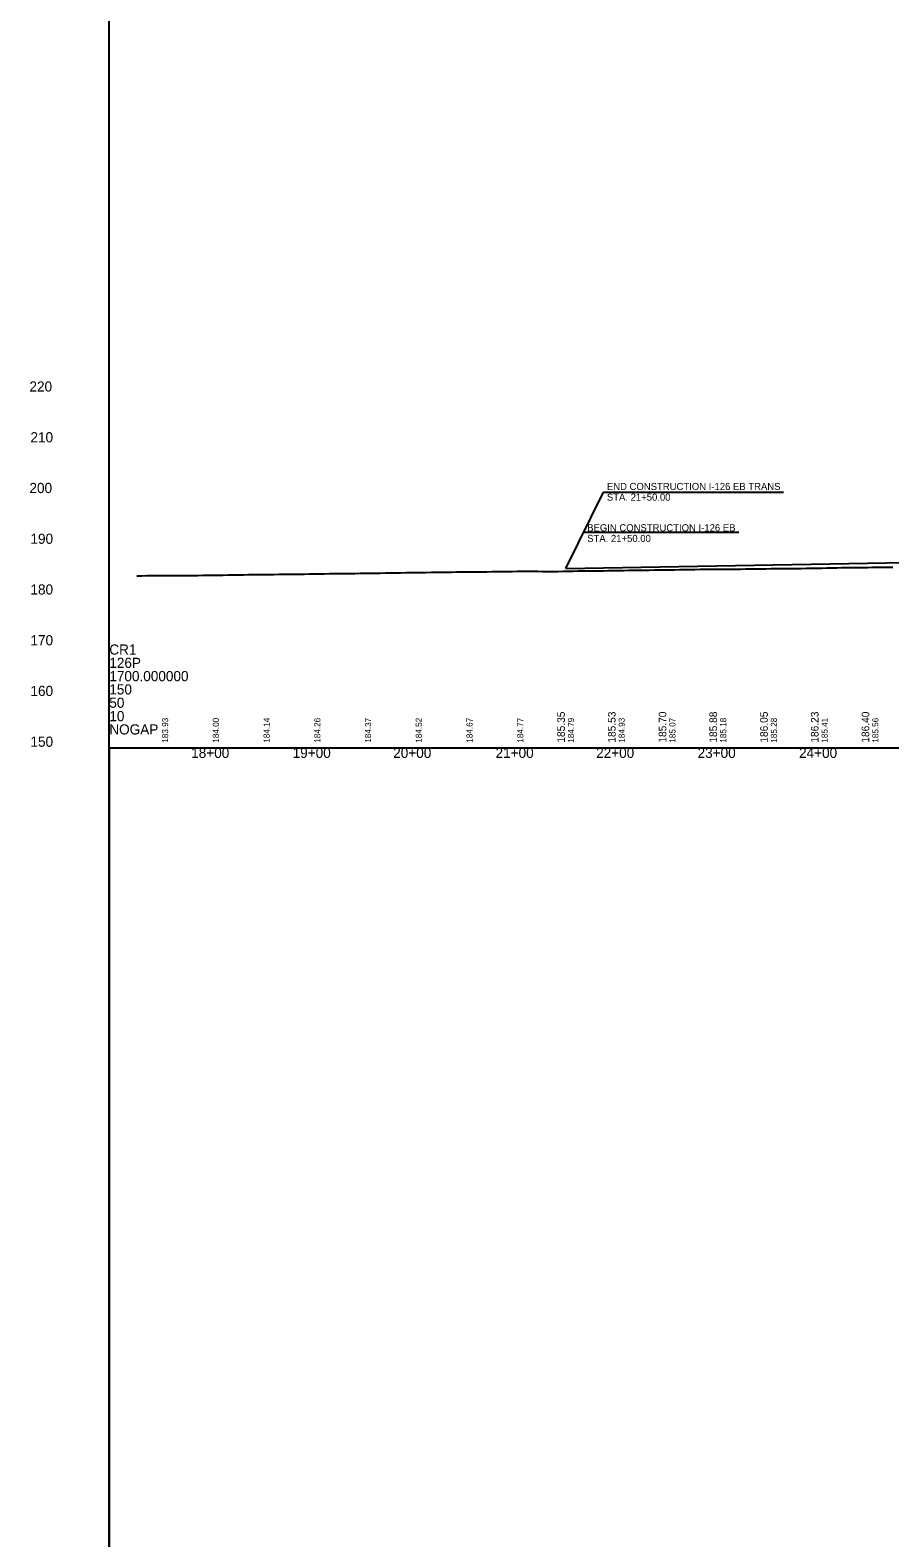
# Model space of a CAD drawing. Extents: x 69 to 2003113, y 512 to 837401.
# Drawn here: x 1888999 to 1889847, y 817230 to 818716 of the extents above; entities that cross this region are included whole.
import ezdxf

# ---------------------------------------------------------------- set-up
doc = ezdxf.new("R2010")
doc.units = 0
for name, color, linetype in [('BR_AUTO DIMENSION', 7, 'Continuous'), ('BR_BORDER LINES', 7, 'Continuous'), ('BR_CONCRETE', 7, 'Continuous'), ('BR_GRID DOTS', 7, 'Continuous'), ('BR_GRID LINES', 7, 'Continuous'), ('BR_TEXT', 7, 'Continuous'), ('MISCELLANEOUS', 7, 'Continuous'), ('RD_HC_Points', 7, 'Continuous'), ('RD_SHT_ID', 7, 'Continuous'), ('RD_SHT_IplotShp', 7, 'Continuous')]:
    doc.layers.add(name, color=color, linetype=linetype)

msp = doc.modelspace()

# ---------------------------------------------------------------- linework, layer by layer
at = {"layer": 'BR_AUTO DIMENSION'}
msp.add_line((1889077.5, 816758.6), (1889077.5, 820132.3), dxfattribs=at)
at = {"layer": 'BR_BORDER LINES'}
for q in [(1889077.5, 819258.6), (1895477.5, 818008.6), (1889077.5, 816758.6)]:
    msp.add_line((1889077.5, 818008.6), q, dxfattribs=at)
at = {"layer": 'BR_GRID DOTS'}
for points in [[(1889527.5, 818185.4), (1889564.6, 818260.4)], [(1889564.6, 818260.4), (1889742.1, 818260.4)], [(1889545.1, 818221), (1889697.9, 818221)]]:
    msp.add_lwpolyline(points, dxfattribs=at)
at = {"layer": 'BR_GRID LINES'}
msp.add_line((1889527.5, 818185.4), (1889927.5, 818192.4), dxfattribs=at)
at = {"layer": 'BR_TEXT'}
for points in [[(1889104.6, 818178.1), (1889109.6, 818178.1), (1889114.6, 818178.2), (1889119.6, 818178.2), (1889124.6, 818178.3), (1889129.6, 818178.3), (1889134.6, 818178.3), (1889139.6, 818178.4), (1889144.6, 818178.4), (1889149.6, 818178.3), (1889154.6, 818178.4), (1889159.6, 818178.4), (1889164.6, 818178.5), (1889169.6, 818178.6), (1889174.6, 818178.6), (1889179.6, 818178.7), (1889184.6, 818178.7), (1889189.6, 818178.8), (1889194.6, 818178.9), (1889199.6, 818178.9), (1889204.6, 818179), (1889209.6, 818179.1), (1889214.6, 818179.2), (1889219.6, 818179.2), (1889224.6, 818179.3), (1889229.6, 818179.3), (1889234.6, 818179.4), (1889239.6, 818179.5), (1889244.6, 818179.6), (1889249.6, 818179.6), (1889254.6, 818179.7), (1889259.6, 818179.7), (1889264.6, 818179.8), (1889269.6, 818179.8), (1889274.6, 818179.9), (1889279.6, 818180), (1889284.6, 818180.1), (1889289.6, 818180.1), (1889294.6, 818180.2), (1889299.6, 818180.3), (1889304.6, 818180.3), (1889309.6, 818180.4), (1889314.6, 818180.4), (1889319.6, 818180.4), (1889324.6, 818180.5), (1889329.6, 818180.5), (1889334.6, 818180.6), (1889339.6, 818180.7), (1889344.6, 818180.8), (1889349.6, 818180.9), (1889354.6, 818181), (1889359.6, 818181), (1889364.6, 818181.1), (1889369.6, 818181.2), (1889374.6, 818181.2), (1889379.6, 818181.3), (1889384.6, 818181.4), (1889389.6, 818181.4), (1889394.6, 818181.5), (1889399.6, 818181.6), (1889404.6, 818181.7), (1889409.6, 818181.7), (1889414.6, 818181.8), (1889419.6, 818181.9), (1889424.6, 818181.9), (1889429.6, 818182), (1889434.6, 818182), (1889439.6, 818182.1), (1889444.6, 818182.1), (1889449.6, 818182.1), (1889454.6, 818182.2), (1889459.6, 818182.3), (1889464.6, 818182.3), (1889469.6, 818182.4), (1889474.6, 818182.4), (1889479.6, 818182.5), (1889484.6, 818182.5), (1889489.6, 818182.6), (1889494.6, 818182.6), (1889499.6, 818182.6), (1889504.6, 818182.4), (1889509.6, 818182.4), (1889514.6, 818182.4), (1889519.6, 818182.4), (1889524.6, 818182.5), (1889529.6, 818182.6), (1889534.6, 818182.7), (1889539.6, 818182.8), (1889544.6, 818182.9), (1889549.6, 818183), (1889554.6, 818183.1), (1889559.6, 818183.1), (1889564.6, 818183.1), (1889569.6, 818183.2), (1889574.6, 818183.3), (1889579.6, 818183.3), (1889584.6, 818183.4), (1889589.6, 818183.5), (1889594.6, 818183.5), (1889599.6, 818183.6), (1889604.6, 818183.7)], [(1889604.6, 818183.7), (1889609.6, 818183.7), (1889614.6, 818183.8), (1889619.6, 818183.9), (1889624.6, 818183.9), (1889629.6, 818184), (1889634.6, 818184.1), (1889639.6, 818184.2), (1889644.6, 818184.3), (1889649.6, 818184.3), (1889654.6, 818184.4), (1889659.6, 818184.5), (1889664.6, 818184.5), (1889669.6, 818184.6), (1889674.6, 818184.5), (1889679.6, 818184.6), (1889684.6, 818184.6), (1889689.6, 818184.7), (1889694.6, 818184.7), (1889699.6, 818184.7), (1889704.6, 818184.8), (1889709.6, 818184.8), (1889714.6, 818184.9), (1889719.6, 818185), (1889724.6, 818185), (1889729.6, 818185.1), (1889734.6, 818185.1), (1889739.6, 818185.1), (1889744.6, 818185.2), (1889749.6, 818185.3), (1889754.6, 818185.4), (1889759.6, 818185.4), (1889764.6, 818185.5), (1889769.6, 818185.6), (1889774.6, 818185.7), (1889779.6, 818185.7), (1889784.6, 818185.8), (1889789.6, 818185.9), (1889794.6, 818186), (1889799.6, 818186.1), (1889804.6, 818186.1), (1889809.6, 818186.2), (1889814.6, 818186.3), (1889819.6, 818186.4), (1889824.6, 818186.4), (1889829.6, 818186.5), (1889834.6, 818186.5), (1889839.6, 818186.6), (1889844.6, 818186.7), (1889849.6, 818186.7)]]:
    msp.add_lwpolyline(points, dxfattribs=at)

# ---------------------------------------------------------------- texts
at = {"layer": 'BR_BORDER LINES'}
for s, p in [('CR1', (1889077.5, 818100.4)), ('126P', (1889077.5, 818087.3)), ('1700.000000', (1889077.5, 818074.2)), ('150', (1889077.5, 818061.1)), ('50', (1889077.5, 818048)), ('10', (1889077.5, 818034.8)), ('NOGAP', (1889077.5, 818021.7))]:
    msp.add_text(s, height=10, dxfattribs=at).set_placement(p)
at = {"layer": 'BR_CONCRETE'}
for s, p in [('183.93', (1889135.5, 818013.6)), ('184.00', (1889185.5, 818013.6)), ('184.14', (1889235.5, 818013.6)), ('184.26', (1889285.5, 818013.6)), ('184.37', (1889335.5, 818013.6)), ('184.52', (1889385.5, 818013.6)), ('184.67', (1889435.5, 818013.6)), ('184.77', (1889485.5, 818013.6)), ('184.79', (1889535.5, 818013.6)), ('184.93', (1889585.5, 818013.6)), ('185.07', (1889635.5, 818013.6)), ('185.18', (1889685.5, 818013.6)), ('185.28', (1889735.5, 818013.6)), ('185.41', (1889785.5, 818013.6)), ('185.56', (1889835.5, 818013.6))]:
    msp.add_text(s, height=6, rotation=90, dxfattribs=at).set_placement(p)
at = {"layer": 'MISCELLANEOUS'}
for s, p in [('220', (1888998.8, 818359.6)), ('210', (1888999.8, 818309.6)), ('200', (1888998.8, 818259.6)), ('190', (1888999.8, 818209.6)), ('180', (1888999.8, 818159.6)), ('170', (1888999.8, 818109.6)), ('160', (1888999.8, 818059.6)), ('150', (1888999.8, 818009.6))]:
    msp.add_text(s, height=10, dxfattribs=at).set_placement(p)
at = {"layer": 'RD_HC_Points'}
for s, p in [('185.35', (1889526.5, 818013.6)), ('185.53', (1889576.5, 818013.6)), ('185.70', (1889626.5, 818013.6)), ('185.88', (1889676.5, 818013.6)), ('186.05', (1889726.5, 818013.6)), ('186.23', (1889776.5, 818013.6)), ('186.40', (1889826.5, 818013.6))]:
    msp.add_text(s, height=7.5, rotation=90, dxfattribs=at).set_placement(p)
at = {"layer": 'RD_SHT_ID'}
for s, p in [('18+00', (1889158.2, 817998.6)), ('19+00', (1889258.2, 817998.6)), ('20+00', (1889357.3, 817998.6)), ('21+00', (1889458.2, 817998.6)), ('22+00', (1889557.3, 817998.6)), ('23+00', (1889657.3, 817998.6)), ('24+00', (1889757.3, 817998.6))]:
    msp.add_text(s, height=10, dxfattribs=at).set_placement(p)
at = {"layer": 'RD_SHT_IplotShp'}
for s, p in [('END CONSTRUCTION I-126 EB TRANS', (1889567.9, 818262.6)), ('STA. 21+50.00', (1889567.9, 818252.1)), ('BEGIN CONSTRUCTION I-126 EB', (1889548.5, 818221.9)), ('STA. 21+50.00', (1889548.5, 818211.4))]:
    msp.add_text(s, height=7, dxfattribs=at).set_placement(p)

doc.saveas('drawing.dxf')
